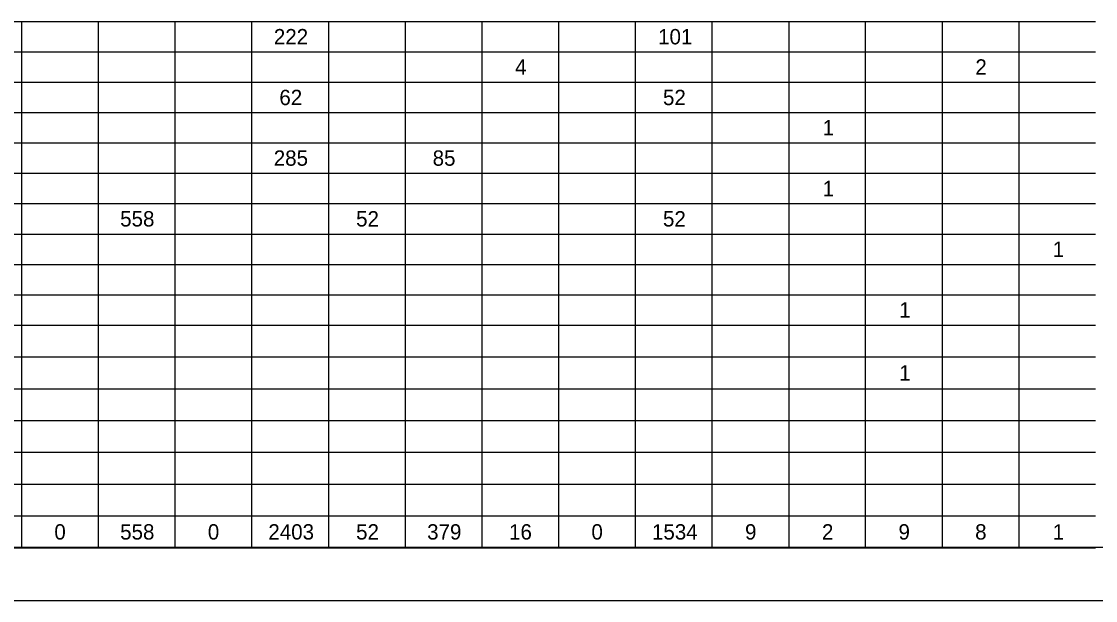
# Model space of a CAD drawing. Extents: x 0 to 34, y 0 to 22.
# Drawn here: x 16.82 to 26.95, y 0 to 5.46 of the extents above; entities that cross this region are included whole.
import ezdxf

# ---------------------------------------------------------------- set-up
doc = ezdxf.new("R2010")
doc.units = 0
for name, color, linetype in [('Default', 7, 'Continuous'), ('SH_Border', 7, 'Continuous'), ('SH_Cut_Line', 7, 'Continuous')]:
    doc.layers.add(name, color=color, linetype=linetype)

msp = doc.modelspace()

# ---------------------------------------------------------------- linework, layer by layer
at = {"layer": 'Default'}
for p, q in [((15.374, 5.462), (16.822, 5.462)), ((16.822, 5.462), (23.336, 5.462)), ((16.822, 5.462), (16.822, 5.175)), ((17.546, 5.462), (17.546, 5.175)), ((18.27, 5.462), (18.27, 5.175)), ((18.993, 5.462), (18.993, 5.175)), ((19.717, 5.462), (19.717, 5.175)), ((20.441, 5.462), (20.441, 5.175)), ((21.165, 5.462), (21.165, 5.175)), ((21.888, 5.462), (21.888, 5.175)), ((22.612, 5.462), (22.612, 5.175)), ((23.336, 5.462), (24.06, 5.462)), ((23.336, 5.462), (23.336, 5.175)), ((24.06, 5.462), (26.231, 5.462)), ((24.06, 5.462), (24.06, 5.175)), ((24.783, 5.462), (24.783, 5.175)), ((25.507, 5.462), (25.507, 5.175)), ((26.231, 5.462), (26.955, 5.462)), ((26.231, 5.462), (26.231, 5.175)), ((15.374, 5.175), (16.822, 5.175)), ((16.822, 5.175), (23.336, 5.175)), ((16.822, 5.175), (16.822, 4.603)), ((17.546, 5.175), (17.546, 4.603)), ((18.27, 5.175), (18.27, 4.603)), ((18.993, 5.175), (18.993, 4.603)), ((19.717, 5.175), (19.717, 4.603)), ((20.441, 5.175), (20.441, 4.603)), ((21.165, 5.175), (21.165, 4.603)), ((21.888, 5.175), (21.888, 4.603)), ((22.612, 5.175), (22.612, 4.603)), ((23.336, 5.175), (24.06, 5.175)), ((23.336, 5.175), (23.336, 4.603)), ((24.06, 5.175), (26.231, 5.175)), ((24.06, 5.175), (24.06, 4.603)), ((24.783, 5.175), (24.783, 4.603)), ((25.507, 5.175), (25.507, 4.603)), ((26.231, 5.175), (26.955, 5.175)), ((26.231, 5.175), (26.231, 4.603)), ((15.374, 4.889), (16.822, 4.889)), ((16.822, 4.889), (23.336, 4.889)), ((23.336, 4.889), (24.06, 4.889)), ((24.06, 4.889), (26.231, 4.889)), ((26.231, 4.889), (26.955, 4.889)), ((15.374, 4.603), (16.822, 4.603)), ((16.822, 4.603), (23.336, 4.603)), ((16.822, 4.603), (16.822, 4.316)), ((17.546, 4.603), (17.546, 4.316)), ((18.27, 4.603), (18.27, 4.316)), ((18.993, 4.603), (18.993, 4.316)), ((19.717, 4.603), (19.717, 4.316)), ((20.441, 4.603), (20.441, 4.316)), ((21.165, 4.603), (21.165, 4.316)), ((21.888, 4.603), (21.888, 4.316)), ((22.612, 4.603), (22.612, 4.316)), ((23.336, 4.603), (24.06, 4.603)), ((23.336, 4.603), (23.336, 4.316)), ((24.06, 4.603), (26.231, 4.603)), ((24.06, 4.603), (24.06, 4.316)), ((24.783, 4.603), (24.783, 4.316)), ((25.507, 4.603), (25.507, 4.316)), ((26.231, 4.603), (26.955, 4.603)), ((26.231, 4.603), (26.231, 4.316)), ((15.374, 4.316), (16.822, 4.316)), ((16.822, 4.316), (23.336, 4.316)), ((16.822, 4.316), (16.822, 4.03)), ((17.546, 4.316), (17.546, 4.03)), ((18.27, 4.316), (18.27, 4.03)), ((18.993, 4.316), (18.993, 4.03)), ((19.717, 4.316), (19.717, 4.03)), ((20.441, 4.316), (20.441, 4.03)), ((21.165, 4.316), (21.165, 4.03)), ((21.888, 4.316), (21.888, 4.03)), ((22.612, 4.316), (22.612, 4.03)), ((23.336, 4.316), (24.06, 4.316)), ((23.336, 4.316), (23.336, 4.03)), ((24.06, 4.316), (26.231, 4.316)), ((24.06, 4.316), (24.06, 4.03)), ((24.783, 4.316), (24.783, 4.03)), ((25.507, 4.316), (25.507, 4.03)), ((26.231, 4.316), (26.955, 4.316)), ((26.231, 4.316), (26.231, 4.03)), ((15.374, 4.03), (16.822, 4.03)), ((16.822, 4.03), (23.336, 4.03)), ((16.822, 4.03), (16.822, 3.744)), ((17.546, 4.03), (17.546, 3.744)), ((18.27, 4.03), (18.27, 3.744)), ((18.993, 4.03), (18.993, 3.744)), ((19.717, 4.03), (19.717, 3.744)), ((20.441, 4.03), (20.441, 3.744)), ((21.165, 4.03), (21.165, 3.744)), ((21.888, 4.03), (21.888, 3.744)), ((22.612, 4.03), (22.612, 3.744)), ((23.336, 4.03), (24.06, 4.03)), ((23.336, 4.03), (23.336, 3.744)), ((24.06, 4.03), (26.231, 4.03)), ((24.06, 4.03), (24.06, 3.744)), ((24.783, 4.03), (24.783, 3.744)), ((25.507, 4.03), (25.507, 3.744)), ((26.231, 4.03), (26.955, 4.03)), ((26.231, 4.03), (26.231, 3.744)), ((15.374, 3.744), (16.822, 3.744)), ((16.822, 3.744), (23.336, 3.744)), ((16.822, 3.744), (16.822, 3.171)), ((17.546, 3.744), (17.546, 3.171)), ((18.27, 3.744), (18.27, 3.171)), ((18.993, 3.744), (18.993, 3.171)), ((19.717, 3.744), (19.717, 3.171)), ((20.441, 3.744), (20.441, 3.171)), ((21.165, 3.744), (21.165, 3.171)), ((21.888, 3.744), (21.888, 3.171)), ((22.612, 3.744), (22.612, 3.171)), ((23.336, 3.744), (24.06, 3.744)), ((23.336, 3.744), (23.336, 3.171)), ((24.06, 3.744), (26.231, 3.744)), ((24.06, 3.744), (24.06, 3.171)), ((24.783, 3.744), (24.783, 3.171)), ((25.507, 3.744), (25.507, 3.171)), ((26.231, 3.744), (26.955, 3.744)), ((26.231, 3.744), (26.231, 3.171)), ((15.374, 3.457), (16.822, 3.457)), ((16.822, 3.457), (23.336, 3.457)), ((23.336, 3.457), (24.06, 3.457)), ((24.06, 3.457), (26.231, 3.457)), ((26.231, 3.457), (26.955, 3.457)), ((15.374, 3.171), (16.822, 3.171)), ((16.822, 3.171), (23.336, 3.171)), ((16.822, 3.171), (16.822, 2.884)), ((17.546, 3.171), (17.546, 2.884)), ((18.27, 3.171), (18.27, 2.884)), ((18.993, 3.171), (18.993, 2.884)), ((19.717, 3.171), (19.717, 2.884)), ((20.441, 3.171), (20.441, 2.884)), ((21.165, 3.171), (21.165, 2.884)), ((21.888, 3.171), (21.888, 2.884)), ((22.612, 3.171), (22.612, 2.884)), ((23.336, 3.171), (24.06, 3.171)), ((23.336, 3.171), (23.336, 2.884)), ((24.06, 3.171), (26.231, 3.171)), ((24.06, 3.171), (24.06, 2.884)), ((24.783, 3.171), (24.783, 2.884)), ((25.507, 3.171), (25.507, 2.884)), ((26.231, 3.171), (26.955, 3.171)), ((26.231, 3.171), (26.231, 2.884)), ((15.374, 2.884), (16.822, 2.884)), ((16.822, 2.884), (23.336, 2.884)), ((16.822, 2.884), (16.822, 2.598)), ((17.546, 2.884), (17.546, 2.598)), ((18.27, 2.884), (18.27, 2.598)), ((18.993, 2.884), (18.993, 2.598)), ((19.717, 2.884), (19.717, 2.598)), ((20.441, 2.884), (20.441, 2.598)), ((21.165, 2.884), (21.165, 2.598)), ((21.888, 2.884), (21.888, 2.598)), ((22.612, 2.884), (22.612, 2.598)), ((23.336, 2.884), (24.06, 2.884)), ((23.336, 2.884), (23.336, 2.598)), ((24.06, 2.884), (26.231, 2.884)), ((24.06, 2.884), (24.06, 2.598)), ((24.783, 2.884), (24.783, 2.598)), ((25.507, 2.884), (25.507, 2.598)), ((26.231, 2.884), (26.955, 2.884)), ((26.231, 2.884), (26.231, 2.598)), ((15.374, 2.598), (16.822, 2.598)), ((16.822, 2.598), (23.336, 2.598)), ((16.822, 2.598), (16.822, 2.298)), ((17.546, 2.598), (17.546, 2.298)), ((18.27, 2.598), (18.27, 2.298)), ((18.993, 2.598), (18.993, 2.298)), ((19.717, 2.598), (19.717, 2.298)), ((20.441, 2.598), (20.441, 2.298)), ((21.165, 2.598), (21.165, 2.298)), ((21.888, 2.598), (21.888, 2.298)), ((22.612, 2.598), (22.612, 2.298)), ((23.336, 2.598), (24.06, 2.598)), ((23.336, 2.598), (23.336, 2.298)), ((24.06, 2.598), (26.231, 2.598)), ((24.06, 2.598), (24.06, 2.298)), ((24.783, 2.598), (24.783, 2.298)), ((25.507, 2.598), (25.507, 2.298)), ((26.231, 2.598), (26.955, 2.598)), ((26.231, 2.598), (26.231, 2.298)), ((15.374, 2.298), (16.822, 2.298)), ((16.822, 2.298), (23.336, 2.298)), ((16.822, 2.298), (16.822, 1.398)), ((17.546, 2.298), (17.546, 1.398)), ((18.27, 2.298), (18.27, 1.398)), ((18.993, 2.298), (18.993, 1.398)), ((19.717, 2.298), (19.717, 1.398)), ((20.441, 2.298), (20.441, 1.398)), ((21.165, 2.298), (21.165, 1.398)), ((21.888, 2.298), (21.888, 1.398)), ((22.612, 2.298), (22.612, 1.398)), ((23.336, 2.298), (24.06, 2.298)), ((23.336, 2.298), (23.336, 1.398)), ((24.06, 2.298), (26.231, 2.298)), ((24.06, 2.298), (24.06, 1.398)), ((24.783, 2.298), (24.783, 1.398)), ((25.507, 2.298), (25.507, 1.398)), ((26.231, 2.298), (26.955, 2.298)), ((26.231, 2.298), (26.231, 1.398)), ((15.374, 1.998), (16.822, 1.998)), ((16.822, 1.998), (23.336, 1.998)), ((23.336, 1.998), (24.06, 1.998)), ((24.06, 1.998), (26.231, 1.998)), ((26.231, 1.998), (26.955, 1.998)), ((15.374, 1.698), (16.822, 1.698)), ((16.822, 1.698), (23.336, 1.698)), ((23.336, 1.698), (24.06, 1.698)), ((24.06, 1.698), (26.231, 1.698)), ((26.231, 1.698), (26.955, 1.698)), ((15.374, 1.398), (16.822, 1.398)), ((16.822, 1.398), (23.336, 1.398)), ((16.822, 1.398), (16.822, 0.798)), ((17.546, 1.398), (17.546, 0.798)), ((18.27, 1.398), (18.27, 0.798)), ((18.993, 1.398), (18.993, 0.798)), ((19.717, 1.398), (19.717, 0.798)), ((20.441, 1.398), (20.441, 0.798)), ((21.165, 1.398), (21.165, 0.798)), ((21.888, 1.398), (21.888, 0.798)), ((22.612, 1.398), (22.612, 0.798)), ((23.336, 1.398), (24.06, 1.398)), ((23.336, 1.398), (23.336, 0.798)), ((24.06, 1.398), (26.231, 1.398)), ((24.06, 1.398), (24.06, 0.798)), ((24.783, 1.398), (24.783, 0.798)), ((25.507, 1.398), (25.507, 0.798)), ((26.231, 1.398), (26.955, 1.398)), ((26.231, 1.398), (26.231, 0.798)), ((15.374, 1.098), (16.822, 1.098)), ((16.822, 1.098), (23.336, 1.098)), ((23.336, 1.098), (24.06, 1.098)), ((24.06, 1.098), (26.231, 1.098)), ((26.231, 1.098), (26.955, 1.098)), ((15.374, 0.798), (16.822, 0.798)), ((16.822, 0.798), (23.336, 0.798)), ((16.822, 0.798), (16.822, 0.498)), ((17.546, 0.798), (17.546, 0.498)), ((18.27, 0.798), (18.27, 0.498)), ((18.993, 0.798), (18.993, 0.498)), ((19.717, 0.798), (19.717, 0.498)), ((20.441, 0.798), (20.441, 0.498)), ((21.165, 0.798), (21.165, 0.498)), ((21.888, 0.798), (21.888, 0.498)), ((22.612, 0.798), (22.612, 0.498)), ((23.336, 0.798), (24.06, 0.798)), ((23.336, 0.798), (23.336, 0.498)), ((24.06, 0.798), (26.231, 0.798)), ((24.06, 0.798), (24.06, 0.498)), ((24.783, 0.798), (24.783, 0.498)), ((25.507, 0.798), (25.507, 0.498)), ((26.231, 0.798), (26.955, 0.798)), ((26.231, 0.798), (26.231, 0.498)), ((15.374, 0.498), (16.822, 0.498)), ((16.822, 0.498), (23.336, 0.498)), ((23.336, 0.498), (24.06, 0.498)), ((24.06, 0.498), (26.231, 0.498)), ((26.231, 0.498), (26.955, 0.498))]:
    msp.add_line(p, q, dxfattribs=at)
at = {"layer": 'SH_Border'}
msp.add_lwpolyline([(1.5, 21.5), (33.5, 21.5), (33.5, 0.5), (1.5, 0.5)], close=True, dxfattribs=at)
at = {"layer": 'SH_Cut_Line'}
msp.add_lwpolyline([(0, 0), (34, 0), (34, 22), (0, 22)], close=True, dxfattribs=at)

# ---------------------------------------------------------------- texts
at = {"layer": 'Default'}
for s, height, p in [('222', 0.1449, (19.203, 5.246)), ('101', 0.1449, (22.828, 5.246)), ('4', 0.145, (21.479, 4.96)), ('2', 0.145, (25.821, 4.96)), ('62', 0.1449, (19.255, 4.673)), ('52', 0.1449, (22.874, 4.673)), ('1', 0.145, (24.38, 4.387)), ('285', 0.1449, (19.202, 4.101)), ('85', 0.1449, (20.701, 4.101)), ('1', 0.145, (24.38, 3.814)), ('558', 0.1449, (17.753, 3.528)), ('52', 0.1449, (19.979, 3.528)), ('52', 0.1449, (22.874, 3.528)), ('1', 0.145, (26.551, 3.241)), ('1', 0.145, (25.103, 2.669)), ('1', 0.145, (25.103, 2.075)), ('0', 0.145, (17.132, 0.575)), ('558', 0.1449, (17.753, 0.575)), ('0', 0.145, (18.58, 0.575)), ('2403', 0.1449, (19.151, 0.575)), ('52', 0.1449, (19.979, 0.575)), ('379', 0.1449, (20.649, 0.575)), ('16', 0.1449, (21.422, 0.575)), ('0', 0.145, (22.199, 0.575)), ('1534', 0.1449, (22.77, 0.575)), ('9', 0.145, (23.648, 0.575)), ('2', 0.145, (24.374, 0.575)), ('9', 0.145, (25.096, 0.575)), ('8', 0.145, (25.819, 0.575)), ('1', 0.145, (26.551, 0.575))]:
    msp.add_text(s, height=height, dxfattribs=at).set_placement(p)

doc.saveas('drawing.dxf')
